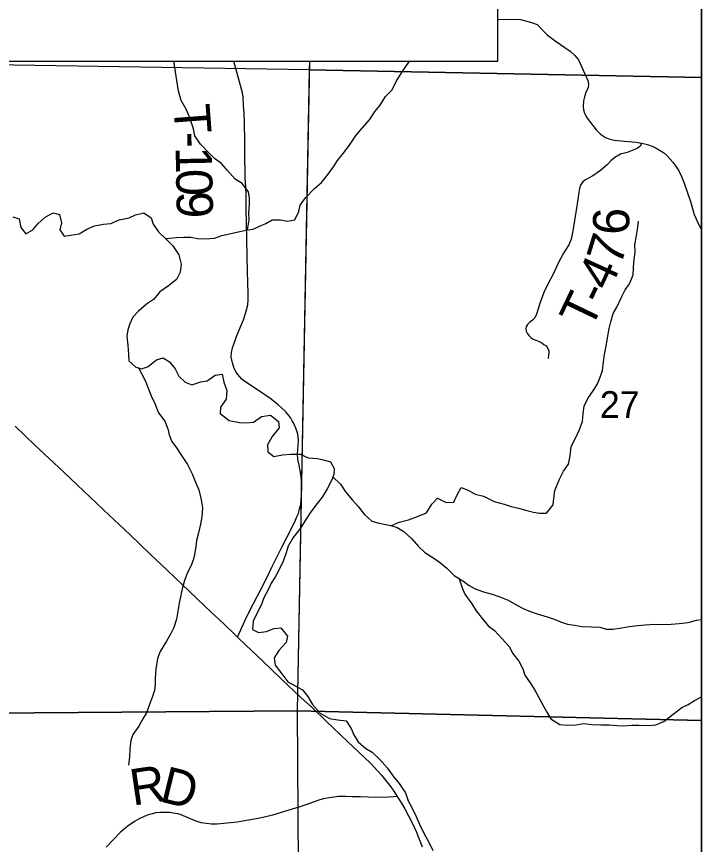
# Model space of a CAD drawing. Extents: x 0 to 34, y 0 to 22.
# Drawn here: x 7.359 to 8.431, y 16.857 to 18.153 of the extents above; entities that cross this region are included whole.
import ezdxf

# ---------------------------------------------------------------- set-up
doc = ezdxf.new("R2010")
doc.units = 0
for name, color, linetype in [('GM_X_Corporation', 7, 'Continuous'), ('GM_X_County_Road', 7, 'Continuous'), ('GM_X_County_Road_Text', 7, 'Continuous'), ('GM_X_Minor_River', 7, 'Continuous'), ('GM_X_Section_Text', 7, 'Continuous'), ('GM_X_State_Route', 7, 'Continuous'), ('GM_X_Township_Road', 7, 'Continuous'), ('GM_X_Township_Road_Text', 7, 'Continuous'), ('SH_Data', 7, 'Continuous'), ('SH_Text', 7, 'Continuous')]:
    doc.layers.add(name, color=color, linetype=linetype)

msp = doc.modelspace()

# ---------------------------------------------------------------- linework, layer by layer
at = {"layer": 'GM_X_Corporation'}
for points in [[(1.6311, 14.5734), (8.4311, 14.5734), (8.4311, 20.028)], [(4.7905, 18.3604), (4.7823, 18.128), (4.7806, 18.0273), (4.765, 16.8754), (4.756, 16.2274), (4.759, 16.0879), (4.9206, 16.0842), (4.928, 16.0841), (4.9731, 16.0831), (4.975, 16.083), (5.0347, 16.0817), (5.0373, 16.0816), (6.4668, 16.045), (6.4721, 16.0449), (6.6873, 16.0404), (6.6909, 16.0403), (6.7034, 16.04), (6.9699, 16.0345), (6.9736, 16.0344), (7.8043, 16.0135), (7.8077, 16.0135), (8.4311, 16.0029), (8.4311, 20.028)], [(7.8172, 18.0831), (7.817, 18.0695), (8.4311, 18.0575), (8.4311, 19.0302), (7.8304, 19.049), (7.8278, 18.8602)], [(7.8172, 18.0831), (7.7982, 17.0659), (6.7684, 17.0582), (6.7857, 18.0831)], [(7.8172, 18.0831), (7.817, 18.0695), (6.9241, 18.0832)]]:
    msp.add_lwpolyline(points, dxfattribs=at)
for points in [[(8.4311, 17.0506), (8.4311, 18.0575), (7.817, 18.0695), (7.7982, 17.0659)], [(7.7982, 17.0659), (7.8046, 16.0144), (6.8244, 16.0368), (6.7585, 16.0372), (6.7684, 17.0582)], [(8.4311, 16.0024), (8.4311, 17.0506), (7.7982, 17.0659), (7.8046, 16.0144)]]:
    msp.add_lwpolyline(points, close=True, dxfattribs=at)
at = {"layer": 'GM_X_County_Road'}
for points in [[(8.1124, 18.1487), (8.1479, 18.148), (8.1576, 18.1458), (8.1667, 18.143), (8.1739, 18.1402), (8.1896, 18.1244), (8.202, 18.1145), (8.2255, 18.0986), (8.2329, 18.0916), (8.2388, 18.0851), (8.246, 18.0688), (8.253, 18.0526), (8.254, 18.0468), (8.2535, 18.0415), (8.2503, 18.0337), (8.2479, 18.0269), (8.2462, 18.0206), (8.2458, 18.0122), (8.2464, 18.0066), (8.2478, 18.0015), (8.2519, 17.9939), (8.2663, 17.9755), (8.2731, 17.9689), (8.2811, 17.9635), (8.2863, 17.9613), (8.2943, 17.9594), (8.3108, 17.9578), (8.3289, 17.9562), (8.3376, 17.9548), (8.3464, 17.9524), (8.3522, 17.9505), (8.3585, 17.9477), (8.3654, 17.9436), (8.3719, 17.9398), (8.3776, 17.9349), (8.3864, 17.925), (8.395, 17.9121), (8.4001, 17.9022), (8.4043, 17.8919), (8.4139, 17.8631), (8.4198, 17.8431), (8.4221, 17.8374), (8.425, 17.8309), (8.429, 17.823), (8.4311, 17.8191)], [(7.9547, 16.9321), (7.9492, 16.9313), (7.941, 16.9309), (7.9213, 16.9305), (7.897, 16.9312), (7.884, 16.9315), (7.874, 16.9319), (7.8627, 16.9317), (7.8552, 16.9309), (7.8479, 16.9298), (7.8389, 16.928), (7.8303, 16.9255), (7.8117, 16.9187), (7.8006, 16.915), (7.7902, 16.9121), (7.7594, 16.9027), (7.7487, 16.9), (7.7371, 16.8973), (7.71, 16.8926), (7.7042, 16.8919), (7.6729, 16.8886), (7.6637, 16.8884), (7.6559, 16.8894), (7.6479, 16.8908), (7.6385, 16.8936), (7.6166, 16.9031), (7.6117, 16.9047), (7.6068, 16.9055), (7.5982, 16.9066), (7.5913, 16.9068), (7.5836, 16.9067), (7.5765, 16.9061), (7.5709, 16.905), (7.5633, 16.9026), (7.5574, 16.9003), (7.5505, 16.8971), (7.5433, 16.8928), (7.5349, 16.887), (7.528, 16.8818), (7.5207, 16.8756), (7.4991, 16.8527)]]:
    msp.add_lwpolyline(points, dxfattribs=at)
at = {"layer": 'GM_X_Minor_River'}
for points in [[(7.5921, 17.8051), (7.6089, 17.8069), (7.6207, 17.8073), (7.6317, 17.8074), (7.6423, 17.8055), (7.654, 17.8048), (7.6684, 17.806), (7.6801, 17.8102), (7.6919, 17.8125), (7.7058, 17.816), (7.7157, 17.8179), (7.7289, 17.8202), (7.7391, 17.8248), (7.749, 17.8286), (7.7588, 17.8343), (7.7721, 17.8344), (7.7827, 17.8325), (7.7944, 17.8348), (7.8004, 17.8478), (7.8027, 17.8576), (7.8113, 17.869), (7.8253, 17.8835), (7.8359, 17.893), (7.8468, 17.9063), (7.8547, 17.9173), (7.8611, 17.9276), (7.8698, 17.9386), (7.88, 17.9515), (7.8906, 17.9671), (7.9, 17.9781), (7.9113, 17.991), (7.9204, 18.0047), (7.9279, 18.0142), (7.9366, 18.0275), (7.9468, 18.0382), (7.9532, 18.0511), (7.9622, 18.0663), (7.9728, 18.0815), (7.974, 18.0831)], [(7.7203, 17.8187), (7.7228, 17.8346), (7.7224, 17.8452), (7.7231, 17.8592), (7.7235, 17.8687), (7.7219, 17.8786), (7.7117, 17.8914), (7.7011, 17.8982), (7.6885, 17.9122), (7.6794, 17.9228), (7.6688, 17.9307), (7.6589, 17.9401), (7.6464, 17.953), (7.638, 17.9658), (7.6357, 17.9768), (7.6296, 17.9954), (7.6243, 18.0079), (7.6163, 18.0215), (7.6124, 18.0359), (7.605, 18.0831)], [(7.3529, 17.8394), (7.3627, 17.836), (7.3651, 17.8228), (7.373, 17.8129), (7.384, 17.819), (7.3919, 17.8285), (7.4033, 17.8388), (7.4157, 17.8453), (7.426, 17.8431), (7.429, 17.8298), (7.4264, 17.8188), (7.4333, 17.809), (7.4431, 17.8105), (7.4567, 17.8128), (7.4684, 17.8201), (7.4805, 17.8251), (7.4949, 17.8278), (7.5063, 17.8286), (7.5195, 17.8347), (7.535, 17.8378), (7.5449, 17.8423), (7.5581, 17.8454), (7.5695, 17.8375), (7.5725, 17.8276), (7.5809, 17.8159), (7.5923, 17.805), (7.6033, 17.7936), (7.6128, 17.78), (7.6163, 17.7653), (7.6148, 17.7524), (7.6091, 17.7413), (7.5963, 17.7311), (7.5831, 17.7219), (7.5729, 17.7101), (7.5623, 17.7025), (7.5495, 17.6915), (7.5408, 17.682), (7.5359, 17.6717), (7.5329, 17.6622), (7.531, 17.6524), (7.5326, 17.6384), (7.5338, 17.624), (7.5345, 17.6141), (7.5456, 17.6039), (7.555, 17.6013), (7.5649, 17.6051), (7.5777, 17.6154), (7.5883, 17.6185), (7.5982, 17.6124), (7.6069, 17.6015), (7.6126, 17.5897), (7.6225, 17.5807), (7.6331, 17.5765), (7.6471, 17.5808), (7.6569, 17.5827), (7.6694, 17.5914), (7.6808, 17.593), (7.6831, 17.5805), (7.6877, 17.5672), (7.6866, 17.554), (7.6779, 17.5411), (7.6772, 17.5312), (7.6916, 17.5203), (7.7079, 17.5173), (7.7185, 17.5169), (7.7294, 17.5177), (7.7423, 17.5269), (7.7563, 17.5288), (7.7688, 17.519), (7.7696, 17.5088), (7.7587, 17.4955), (7.7515, 17.4822), (7.7519, 17.4716), (7.7614, 17.464), (7.775, 17.4667), (7.7883, 17.4679)], [(7.9455, 17.3559), (7.9578, 17.3612), (7.9722, 17.3647), (7.9862, 17.37), (8.0006, 17.3761), (8.0089, 17.3894), (8.0176, 17.3989), (8.0312, 17.3922), (8.0433, 17.3926), (8.0478, 17.4028), (8.055, 17.4154), (8.066, 17.4112), (8.077, 17.4052), (8.0899, 17.4018), (8.1066, 17.3936), (8.1221, 17.3894), (8.1331, 17.3857), (8.1448, 17.3831), (8.1577, 17.3797), (8.1679, 17.3771), (8.1774, 17.3756), (8.1884, 17.3753), (8.199, 17.3886), (8.2001, 17.3984), (8.2015, 17.4109), (8.2087, 17.4284), (8.2151, 17.4409), (8.223, 17.4519), (8.2256, 17.4652), (8.2271, 17.48), (8.2346, 17.4937), (8.2403, 17.5066), (8.2448, 17.5187), (8.2459, 17.5312), (8.2473, 17.543), (8.253, 17.5548), (8.2624, 17.5685), (8.2681, 17.5779), (8.2726, 17.5882), (8.276, 17.5988), (8.2778, 17.6121), (8.2793, 17.6239), (8.2819, 17.6368), (8.2838, 17.6496), (8.2867, 17.6644), (8.289, 17.6747), (8.2931, 17.688), (8.2988, 17.6978), (8.3067, 17.7145), (8.3119, 17.7248), (8.3183, 17.7343), (8.3244, 17.7483), (8.3247, 17.7582), (8.3254, 17.7684), (8.3273, 17.784), (8.3269, 17.7953), (8.3287, 17.8071), (8.331, 17.8196), (8.3324, 17.8325)], [(7.5493, 17.6029), (7.5604, 17.582), (7.5646, 17.571), (7.5695, 17.5589), (7.5753, 17.5472), (7.581, 17.5324), (7.5909, 17.5195), (7.5954, 17.5074), (7.5977, 17.498), (7.6016, 17.4877), (7.6088, 17.4779), (7.6171, 17.4658), (7.6263, 17.4518), (7.6335, 17.4367), (7.6389, 17.4238), (7.6442, 17.4117), (7.6476, 17.3965), (7.6496, 17.3837), (7.6485, 17.3696), (7.6466, 17.3582), (7.6436, 17.3446), (7.6406, 17.3328), (7.6395, 17.3234), (7.6377, 17.3131), (7.6354, 17.3036), (7.6317, 17.2922), (7.6264, 17.2824), (7.6215, 17.2698), (7.6185, 17.2592), (7.6166, 17.2497), (7.6133, 17.2346), (7.6114, 17.2251), (7.6088, 17.2095), (7.6047, 17.1966), (7.6002, 17.1868), (7.5934, 17.175), (7.5836, 17.1586), (7.5795, 17.148), (7.5765, 17.1313), (7.5754, 17.1177), (7.5754, 17.1078), (7.5747, 17.098), (7.5717, 17.0885), (7.5668, 17.076), (7.5619, 17.0631), (7.5563, 17.0532), (7.5502, 17.0422), (7.5404, 17.0289), (7.5374, 17.0194), (7.536, 17.0065), (7.5356, 16.994), (7.5338, 16.9807)], [(7.7883, 17.4679), (7.8027, 17.4676), (7.8152, 17.4619), (7.83, 17.4608), (7.8409, 17.4586), (7.8504, 17.4556), (7.8557, 17.4454), (7.8554, 17.4359), (7.8516, 17.4264), (7.8452, 17.4135), (7.8369, 17.4002), (7.8294, 17.3907), (7.8192, 17.3774), (7.8105, 17.3641), (7.803, 17.352), (7.7917, 17.3371), (7.7838, 17.3238), (7.7804, 17.3117), (7.7763, 17.3003), (7.7703, 17.2882), (7.7642, 17.2764), (7.7571, 17.2658), (7.7533, 17.2563), (7.7454, 17.2418), (7.7424, 17.2324), (7.736, 17.2202), (7.7289, 17.2062), (7.7278, 17.1933), (7.7372, 17.1884), (7.7501, 17.1899), (7.7614, 17.1949), (7.7724, 17.1961), (7.7827, 17.1828), (7.7808, 17.173), (7.7695, 17.1604), (7.762, 17.149), (7.7635, 17.1377), (7.7738, 17.1237), (7.7833, 17.1116), (7.7939, 17.1055), (7.8064, 17.0988), (7.8148, 17.0886), (7.822, 17.0761), (7.8338, 17.0625), (7.8486, 17.0538), (7.8618, 17.0519), (7.8747, 17.0505), (7.8827, 17.0384), (7.8869, 17.0285), (7.8934, 17.0172), (7.9055, 17.007), (7.9157, 17.0013), (7.9275, 16.99), (7.9393, 16.976), (7.948, 16.9643), (7.9579, 16.9522), (7.9674, 16.9375), (7.972, 16.925), (7.9777, 16.9147), (7.9846, 16.9004), (7.9895, 16.8886), (7.9968, 16.8735), (8.004, 16.8606), (8.0105, 16.8474)], [(7.8539, 17.4322), (7.866, 17.4208), (7.8736, 17.4087), (7.8847, 17.3955), (7.8934, 17.3856), (7.9037, 17.3735), (7.9147, 17.363), (7.9245, 17.36), (7.934, 17.3581), (7.9446, 17.3562), (7.9548, 17.3529), (7.9651, 17.3465), (7.9776, 17.3351), (7.9882, 17.323), (7.9981, 17.314), (8.0118, 17.3049), (8.0228, 17.297), (8.0323, 17.2891), (8.044, 17.2777), (8.0573, 17.2694), (8.0676, 17.2623), (8.077, 17.257), (8.0896, 17.2521), (8.1032, 17.2484), (8.1153, 17.2446), (8.1282, 17.2394), (8.1419, 17.2314), (8.1521, 17.2262), (8.162, 17.222), (8.1737, 17.2179), (8.1896, 17.213), (8.2006, 17.2093), (8.2105, 17.2055), (8.2215, 17.2018), (8.2321, 17.2003), (8.2438, 17.1981), (8.259, 17.1977), (8.2718, 17.197), (8.2825, 17.194), (8.2923, 17.1937), (8.3067, 17.196), (8.318, 17.1979), (8.3317, 17.1995), (8.343, 17.2007), (8.3578, 17.2015), (8.3695, 17.2011), (8.3839, 17.2016), (8.3964, 17.2027), (8.4104, 17.2043), (8.4236, 17.2081), (8.4311, 17.2088)], [(8.0519, 17.2728), (8.0566, 17.2584), (8.0604, 17.2486), (8.0718, 17.2335), (8.0783, 17.2225), (8.0885, 17.21), (8.0973, 17.1991), (8.1072, 17.1915), (8.1185, 17.1791), (8.1303, 17.1662), (8.1353, 17.156), (8.1452, 17.1435), (8.1516, 17.1318), (8.1543, 17.1216), (8.1638, 17.1083), (8.1703, 17.0981), (8.1764, 17.0868), (8.184, 17.0735), (8.1889, 17.0637), (8.1954, 17.0535), (8.2091, 17.0444), (8.2212, 17.0437), (8.2348, 17.0441), (8.2462, 17.0464), (8.259, 17.0446), (8.2734, 17.0443), (8.2867, 17.0443), (8.2988, 17.0428), (8.309, 17.0425), (8.3223, 17.0433), (8.3329, 17.0433), (8.3495, 17.043), (8.3598, 17.0438), (8.3722, 17.0495), (8.387, 17.0609), (8.4006, 17.0712), (8.4104, 17.0758), (8.4202, 17.0819), (8.4311, 17.0878)]]:
    msp.add_lwpolyline(points, dxfattribs=at)
at = {"layer": 'GM_X_State_Route'}
msp.add_lwpolyline([(7.3562, 17.5114), (7.3868, 17.4825), (7.4324, 17.4398), (7.4641, 17.4096), (7.5035, 17.3725), (7.5195, 17.3574), (7.5363, 17.3417), (7.5679, 17.3113), (7.5947, 17.2859), (7.6288, 17.2535), (7.6535, 17.2299), (7.6633, 17.2206), (7.6824, 17.2025), (7.7008, 17.1849), (7.7045, 17.1815), (7.7178, 17.1688), (7.7438, 17.1441), (7.7737, 17.1158), (7.8045, 17.0863), (7.8218, 17.0705), (7.8436, 17.0498), (7.8773, 17.0173), (7.9124, 16.9844), (7.93, 16.9655), (7.9447, 16.947), (7.9506, 16.9387), (7.9547, 16.9321), (7.9616, 16.9213), (7.9668, 16.9128), (7.9725, 16.9017), (7.9793, 16.8884), (7.9843, 16.8769), (7.9937, 16.8531)], dxfattribs=at)
at = {"layer": 'GM_X_Township_Road'}
for points in [[(7.7045, 17.1815), (7.7158, 17.2067), (7.7246, 17.2243), (7.7404, 17.255), (7.7513, 17.2763), (7.7584, 17.2907), (7.7745, 17.3232), (7.7818, 17.3374), (7.7931, 17.3599), (7.7952, 17.3642), (7.7977, 17.3697), (7.8, 17.375), (7.8019, 17.382), (7.8035, 17.3892), (7.8049, 17.4032), (7.8049, 17.4178), (7.8047, 17.427), (7.8039, 17.4358), (7.8012, 17.4504), (7.7993, 17.4601), (7.7985, 17.4682), (7.7991, 17.4745), (7.8001, 17.489), (7.7997, 17.4957), (7.7984, 17.5013), (7.7959, 17.5085), (7.7934, 17.5146), (7.7904, 17.5199), (7.788, 17.5239), (7.7849, 17.5282), (7.7801, 17.534), (7.7739, 17.5398), (7.768, 17.5452), (7.7575, 17.5538), (7.7389, 17.5662), (7.7159, 17.5815), (7.7115, 17.5851), (7.7082, 17.5887), (7.7049, 17.5923), (7.7024, 17.5961), (7.6994, 17.6021), (7.6966, 17.6108), (7.6948, 17.6194), (7.6952, 17.6268), (7.6965, 17.6344), (7.7012, 17.6471), (7.7036, 17.6536), (7.7138, 17.6778), (7.7173, 17.6878), (7.7189, 17.6935), (7.7205, 17.7017), (7.7212, 17.7094), (7.7212, 17.7201), (7.7207, 17.7352), (7.7197, 17.7749), (7.7192, 17.8076), (7.7185, 17.826), (7.7182, 17.8539), (7.7181, 17.8732), (7.7176, 17.8864), (7.7168, 17.9001), (7.7161, 17.9403), (7.7159, 17.9589), (7.7153, 17.9864), (7.7149, 18.0009), (7.7142, 18.0141), (7.7135, 18.0266), (7.7125, 18.0332), (7.6989, 18.0831)], [(8.3376, 17.9548), (8.3349, 17.9498), (8.3306, 17.946), (8.3228, 17.9429), (8.3147, 17.9398), (8.3042, 17.9374), (8.2957, 17.9321), (8.2891, 17.9269), (8.2836, 17.9209), (8.2731, 17.9116), (8.2608, 17.9034), (8.2496, 17.8971), (8.2448, 17.8933), (8.2419, 17.8888), (8.24, 17.8836), (8.2389, 17.8776), (8.2376, 17.8663), (8.235, 17.8498), (8.2296, 17.8174), (8.2273, 17.8043), (8.2233, 17.7952), (8.2186, 17.7879), (8.2149, 17.7822), (8.2108, 17.7748), (8.2074, 17.7679), (8.1985, 17.7487), (8.1905, 17.7339), (8.1845, 17.7209), (8.1781, 17.7037), (8.176, 17.6969), (8.1727, 17.6869), (8.1702, 17.6813), (8.1664, 17.6775), (8.1617, 17.674), (8.1588, 17.6709), (8.1568, 17.6678), (8.1561, 17.6635), (8.1568, 17.6602), (8.1582, 17.657), (8.1607, 17.6534), (8.1645, 17.6499), (8.1678, 17.6478), (8.1719, 17.646), (8.1768, 17.6442), (8.1812, 17.6422), (8.1845, 17.6396), (8.1881, 17.6371), (8.1907, 17.6334), (8.1919, 17.6297), (8.1921, 17.6263), (8.1918, 17.6226), (8.1913, 17.6173)]]:
    msp.add_lwpolyline(points, dxfattribs=at)
at = {"layer": 'SH_Data'}
msp.add_lwpolyline([(5.6652, 18.0831), (8.1124, 18.0831), (8.1124, 18.8602), (5.6652, 18.8602)], close=True, dxfattribs=at)
at = {"layer": 'SH_Text'}
msp.add_line((8.4311, 21.373), (8.4311, 14.5734), dxfattribs=at)

# ---------------------------------------------------------------- texts
at = {"layer": 'GM_X_County_Road_Text'}
for s, rotation, p in [('R', 8.3465, (7.5405, 16.9175)), ('D', 346.1617, (7.5809, 16.9246))]:
    msp.add_text(s, height=0.0568, rotation=rotation, dxfattribs=at).set_placement(p)
at = {"layer": 'GM_X_Section_Text'}
msp.add_text('27', height=0.04186, rotation=0, dxfattribs=at).set_placement((8.272, 17.5245))
at = {"layer": 'GM_X_Township_Road_Text'}
for s, rotation, p in [('T', 274.2939, (7.604, 18.0136)), ('-', 271.1007, (7.6071, 17.972)), ('1', 271.1068, (7.6076, 17.9487)), ('0', 271.1033, (7.6082, 17.9137)), ('9', 271.1068, (7.6089, 17.8787)), ('6', 88.2963, (8.3175, 17.8105)), ('7', 72.8388, (8.3044, 17.7606)), ('4', 65.2653, (8.2869, 17.7212)), ('-', 64.4772, (8.2764, 17.6993)), ('T', 64.3377, (8.258, 17.6609))]:
    msp.add_text(s, height=0.0568, rotation=rotation, dxfattribs=at).set_placement(p)

doc.saveas('drawing.dxf')
